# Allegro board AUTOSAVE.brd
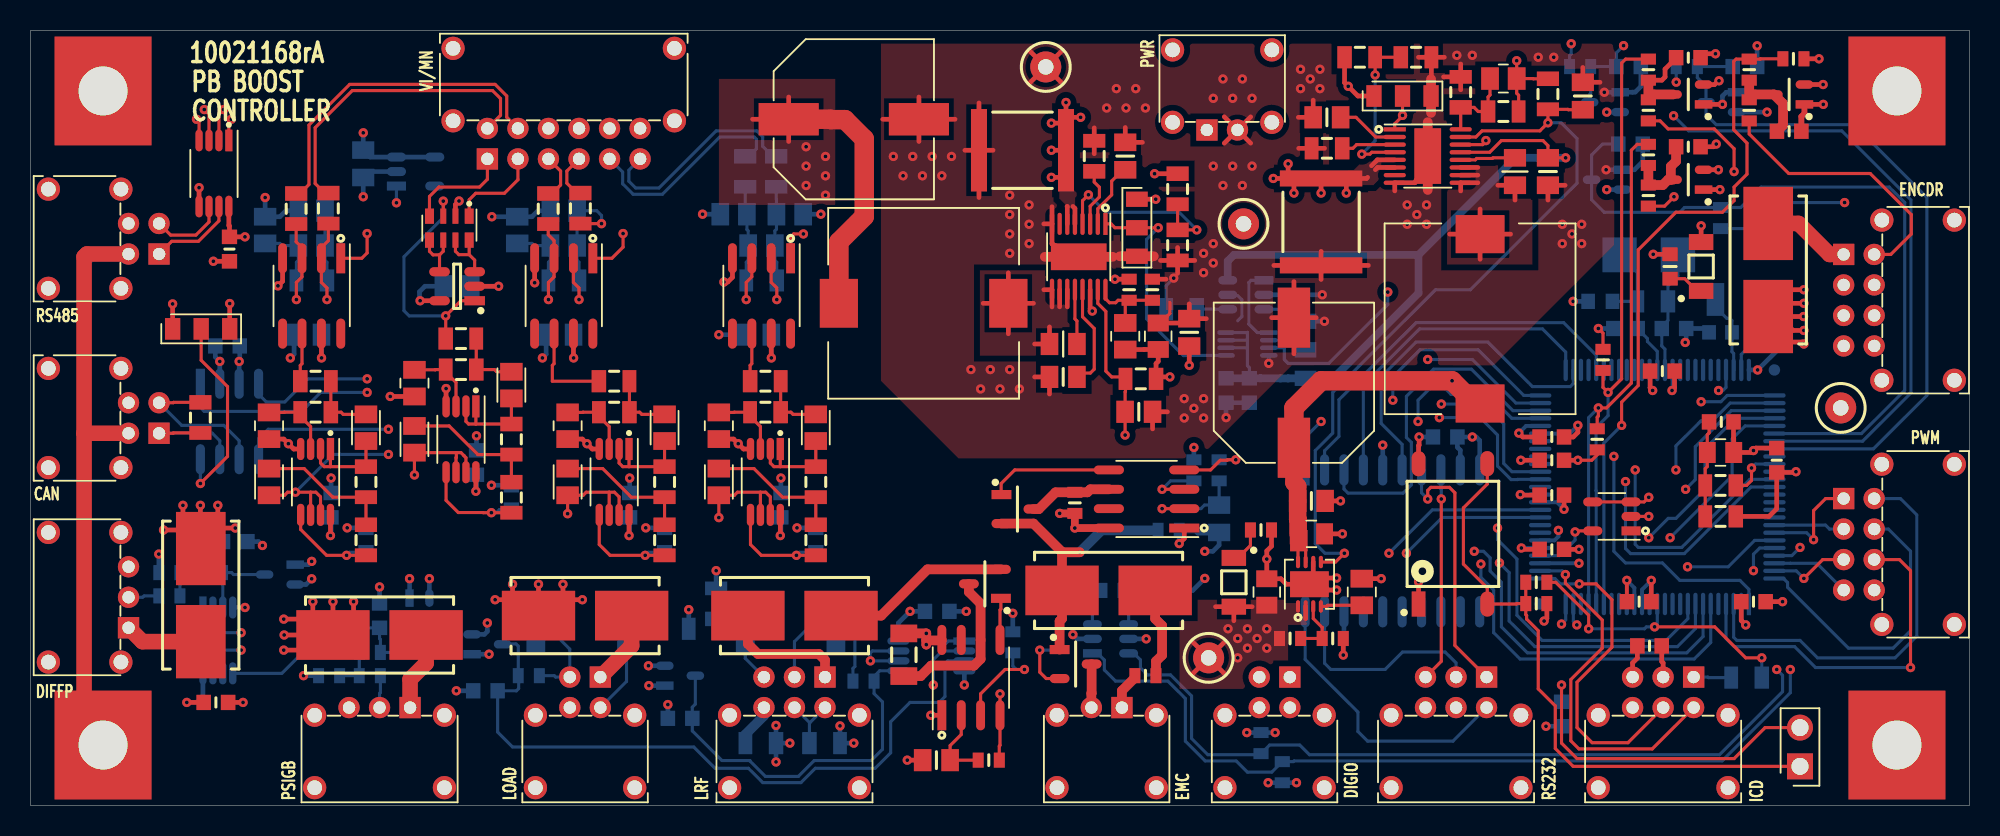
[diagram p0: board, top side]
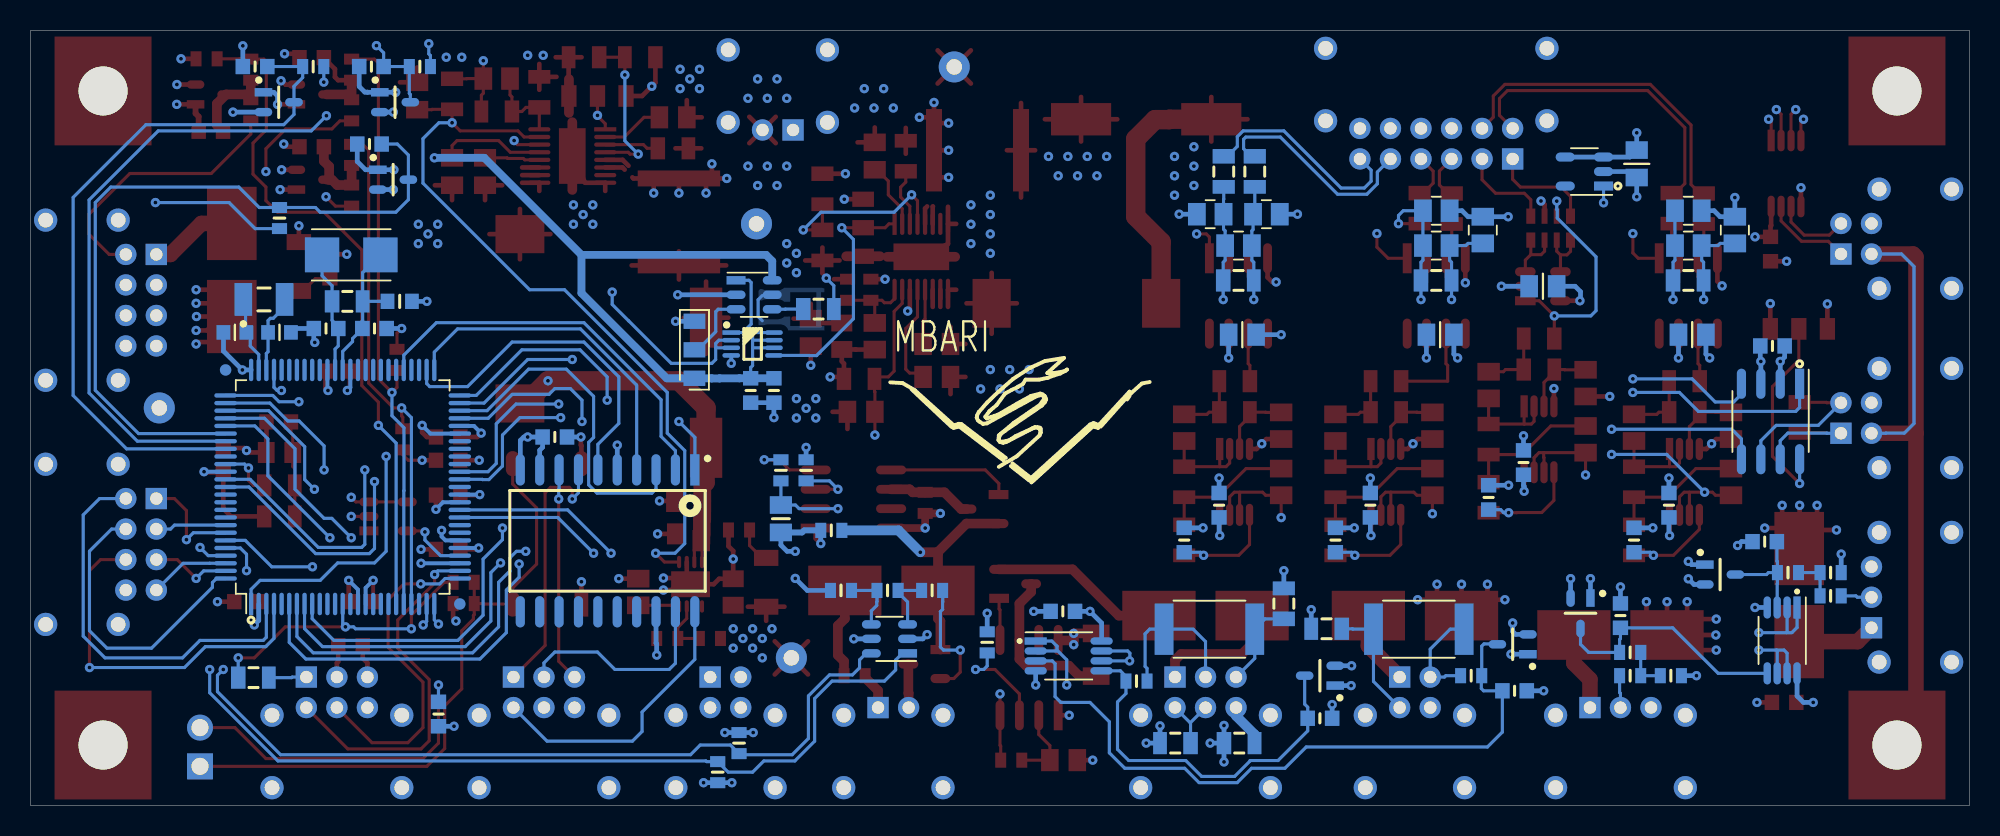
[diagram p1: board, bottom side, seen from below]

Outline 127 x 50.8 mm; copper layers: TOP, GND1, PWR, INR1, GND2, BOTTOM. Coordinates in mm from the lower left corner of the outline.
Outline path: 0,50.8 0,0 127,0 127,50.8 0,50.8

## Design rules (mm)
net group ASIG_IBOOST: nets ASIG_IBOOST+ ASIG_IBOOST-
net group ASIG_IBUS: nets ASIG_IBUS+ ASIG_IBUS-
net group ASIG_ILOAD: nets ASIG_ILOAD+ ASIG_ILOAD-
net group ASIG_VBUS: nets ASIG_VBUS+ ASIG_VBUS-

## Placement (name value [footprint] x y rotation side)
C1  10uF  [CAPC2012X135N]  110.69 23.14 0 top
C2  0.10uF  [CAPC1608X87N]  110.74 25.15 0 top
C3  0.10uF  [CAPC1608X87N]  100.28 5.99 270 bottom
C4  22pF  [CAPC1608X90N_G100]  113.61 31.01 0 bottom
C5  22pF  [CAPC1608X90N_G100]  110.69 31.01 180 bottom
C6  33pF  [CAPC1608X90N]  104.47 31.27 180 bottom
C7  33pF  [CAPC1608X90N]  107.65 31.27 0 bottom
C8  0.10uF  [CAPC1608X87N]  112.85 13.36 0 top
C9  0.10uF  [CAPC1608X87N]  105.36 13.36 0 top
C10  0.10uF  [CAPC1608X87N]  99.64 16.79 0 top
C11  0.10uF  [CAPC1608X87N]  99.64 20.35 0 top
C12  0.10uF  [CAPC1608X87N]  99.64 24.16 0 top
C13  0.10uF  [CAPC1608X87N]  106.88 28.47 0 top
C14  0.10uF  [CAPC1608X87N]  114.38 22.63 90 top
C15  0.10uF  [CAPC1608X87N]  99.64 22.63 0 top
C16  10.0pF  [CAPC2012X88N]  96.47 47.65 0 top
C17  1.0uF  [CAPC2012X140N]  99.39 41.55 270 top
C18  0.1uF  [CAPC2013X94N]  97.23 41.55 270 top
C19  0.10uF  [CAPC2012X110N]  84.91 45.11 180 top
C20  10uF  [CAPC5750X250N]  84.53 38.25 270 top
C21  10uF  [CAPC2012X135N]  83.9 17.81 0 top
C22  0.10uF  [CAPC2012X110N]  83.9 19.96 0 top
C23  2200uF  [CAPAE1030X1380DD450L320N]  82.75 27.71 90 top
C24  10uF  [CAPC2012X135N]  80.98 14 90 top
C25  0.10uF  [CAPC2012X100N]  101.68 46.51 90 top
C26  1000.0pF  [CAPC2012X88N]  87.2 14 90 top
C27  0.10uF  [CAPC1608X87N]  78.31 27.2 270 bottom
C28  0.10uF  [CAPC1608X87N]  79.83 27.2 270 bottom
C29  10.0pF  [CAPC2012X88N]  71.7 30.76 270 top
C30  1.0uF  [CAPC2012X140N]  67.64 28.09 180 top
C31  0.1uF  [CAPC2013X94N]  67.64 30.25 180 top
C32  0.10uF  [CAPC2012X110N]  71.7 42.57 90 top
C33  10uF  [CAPC5750X250N]  64.97 42.95 180 top
C34  10uF  [CAPC2012X135N]  73.86 30.76 90 top
C35  0.10uF  [CAPC2012X110N]  75.9 31.01 90 top
C36  2200uF  [CAPAE1030X1380DD450L320N]  53.92 44.98 0 top
C37  0.10uF  [CAPC2012X100N]  72.59 25.81 0 top
C38  0.10uF  [CAPC1608X87N]  12.9 30.12 180 bottom
C39  0.10uF  [CAPC1608X87N]  106.05 10.46 180 top
C40  0.10uF  [CAPC1608X87N]  13.03 36.47 270 top
C41  0.10uF  [CAPC1608X87N]  92.66 24.16 180 bottom
C42  0.1uF  [CAPC2013X94N]  27.94 34.04 0 bottom
C43  680pF  [CAPC2012X88N]  25.15 27.69 270 top
C44  560pF  [CAPC1608X90N]  31.5 20.19 90 bottom
C45  6800pF  [CAPC2012X90N]  31.5 27.56 270 top
C46  6800pF  [CAPC2012X90N]  25.15 24 270 top
C47  0.10uF  [CAPC1608X87N]  29.21 22.48 90 bottom
C48  10,000.0pF  [CAPC2012X88N]  34.92 38.99 0 bottom
C49  0.1uF  [CAPC2013X94N]  34.67 30.86 180 bottom
C50  10,000.0pF  [CAPC2012X88N]  34.92 36.7 180 bottom
C51  680pF  [CAPC2012X88N]  35.18 24.89 270 top
C52  560pF  [CAPC1608X90N]  41.53 17.4 90 bottom
C53  10,000.0pF  [CAPC2012X88N]  31.88 37.72 90 bottom
C54  6800pF  [CAPC2012X90N]  41.53 24.77 270 top
C55  6800pF  [CAPC2012X90N]  35.18 21.21 270 top
C56  0.10uF  [CAPC1608X87N]  39.24 19.68 90 bottom
C57  10,000.0pF  [CAPC2012X88N]  49.73 38.76 180 bottom
C58  0.1uF  [CAPC2013X94N]  47.62 30.86 180 bottom
C59  10,000.0pF  [CAPC2012X88N]  47.88 36.7 180 bottom
C60  680pF  [CAPC2012X88N]  45.09 24.89 270 top
C61  560pF  [CAPC1608X90N]  51.44 17.4 90 bottom
C62  10,000.0pF  [CAPC2012X88N]  46.05 38.76 180 bottom
C63  6800pF  [CAPC2012X90N]  51.44 24.77 270 top
C64  6800pF  [CAPC2012X90N]  45.09 21.21 270 top
C65  0.10uF  [CAPC1608X87N]  49.15 19.68 90 bottom
C66  10,000.0pF  [CAPC2012X88N]  18.41 38.99 0 bottom
C67  0.1uF  [CAPC2013X94N]  18.16 30.86 180 bottom
C68  10,000.0pF  [CAPC2012X88N]  18.41 36.7 180 bottom
C69  680pF  [CAPC2012X88N]  15.62 24.89 270 top
C70  560pF  [CAPC1608X90N]  21.97 17.4 90 bottom
C71  10,000.0pF  [CAPC2012X88N]  15.37 37.72 90 bottom
C72  6800pF  [CAPC2012X90N]  21.97 24.77 270 top
C73  6800pF  [CAPC2012X90N]  15.62 21.21 270 top
C74  0.10uF  [CAPC1608X87N]  19.68 19.68 90 bottom
C75  0.1uF  [CAPC2013X94N]  21.79 42.06 270 bottom
C76  0.10uF  [CAPC1608X87N]  13.41 17.3 0 bottom
C77  0.10uF  [CAPC1608X87N]  22.86 12.45 90 bottom
C78  0.10uF  [CAPC1608X87N]  29.79 7.52 180 bottom
C79  0.10uF  [CAPC1608X87N]  42.55 5.71 180 bottom
C80  0.10uF  [CAPC1608X87N]  12.14 6.76 0 top
C81  0.10uF  [CAPC1608X87N]  59.39 12.73 0 bottom
C82  0.47uF  [CAPC1608X87N]  104.8 43.36 0 bottom
C83  4.7uF  [CAPC2012X140N]  59.33 2.97 180 top
C84  0.47uF  [CAPC1608X87N]  104.67 48.44 0 bottom
C85  0.47uF  [CAPC1608X87N]  112.29 48.44 0 bottom
C86  4.7uF  [CAPC2012X140N]  77.85 18.8 270 bottom
C87  0.47uF  [CAPC1608X87N]  108.58 49.02 0 top
C88  0.47uF  [CAPC1608X87N]  108.58 43.18 0 top
C89  0.47uF  [CAPC1608X87N]  115.19 44.2 0 top
D1  LTST-C150KGKT  [LED_LTST-C150XXX]  78.82 14.63 270 top
D2  LTST-C150KGKT  [LED_LTST-C150XXX]  109.42 35.33 90 top
DN1  BAT54SWT1G  [SOT65P220X100-3N_132]  29.92 10.57 0 bottom
DN2  BAT54SWT1G  [SOT65P220X100-3N_132]  42.55 8.51 0 bottom
DN3  BAT54SWT1G  [SOT65P220X100-3N_132]  108.58 41.02 180 top
DN4  BAT54SWT1G  [SOT65P220X100-3N_132]  108.58 46.61 180 top
DN5  BAT54SWT1G  [SOT65P220X100-3N_132]  115.19 46.61 180 top
DN6  BAT54SWT1G  [SOT65P220X100-3N_132]  103.25 41.02 180 bottom
DN7  BAT54SWT1G  [SOT65P220X100-3N_132]  103.12 46.1 180 bottom
DN8  BAT54SWT1G  [SOT65P220X100-3N_132]  110.74 46.1 180 bottom
DN9  BAT54SWT1G  [SOT65P220X100-3N_132]  25.48 12.6 270 bottom
DN10  BAT54SWT1G  [SOT65P220X100-3N_132]  16.33 15.14 180 bottom
F1  0154.125DR  [FUSM9750X381N]  11.15 13.79 90 top
F2  0154.125DR  [FUSM9750X381N]  22.86 11.18 180 top
F3  0154.125DR  [FUSM9750X381N]  36.32 12.45 180 top
F4  0154.125DR  [FUSM9750X381N]  50.04 12.45 0 top
F5  0154.125DR  [FUSM9750X381N]  113.82 35.1 270 top
F6  0154.125DR  [FUSM9750X381N]  70.61 14.1 180 top
J1  M80-8420242  [HARWIN_M80-8420242]  78.05 47.65 180 top
J2  M80-8510442  [HARWIN_M80-8510442]  3.05 25.4 270 top
J3  M80-8510642  [HARWIN_M80-8510642]  106.93 3.05 0 top
J4  M80-8510442  [HARWIN_M80-8510442]  3.05 37.15 270 top
J5  M80-8510642  [HARWIN_M80-8510642]  93.37 3.05 0 top
J6  M80-8511242  [HARWIN_M80-8511242]  34.92 47.75 180 top
J7  M80-8420342  [HARWIN_M80-8420342]  3.05 13.65 270 top
J8  M80-8420342  [HARWIN_M80-8420342]  22.86 3.05 0 top
J9  M80-8510442  [HARWIN_M80-8510442]  36.32 3.05 0 top
J10  M80-8510642  [HARWIN_M80-8510642]  50.04 3.05 0 top
J11  M80-8510842  [HARWIN_M80-8510842]  124.13 33.12 90 top
J12  M80-8510842  [HARWIN_M80-8510842]  124.13 17.12 90 top
J13  M80-8420242  [HARWIN_M80-8420242]  70.48 3.05 0 top
J14  M80-8510442  [HARWIN_M80-8510442]  81.48 3.05 0 top
JP1  LS=0.100"  [HDRV2W64P254_2X1_508X254H1363B]  115.9 2.57 90 top
JR1  TBD  [MISC_0805-3P-JMPR]  89.87 46.51 0 top
JR2  TBD  [MISC_0805-3P-JMPR]  83.52 29.87 90 bottom
JR3  TBD  [MISC_0805-3P-JMPR]  72.47 37.87 270 top
JR4  TBD  [MISC_0805-3P-JMPR]  11.18 31.24 0 top
L1  220uH  [IND_NS-12]  94.95 31.9 270 top
L2  220uH  [IND_NS-12]  58.5 32.92 180 top
NOREF  -  []  0 0 0 top
NOREF#2  -  []  256.03 33.78 0 top
NOREF#3  -  []  144.78 -66.04 0 top
NOREF#4  -  []  0 0 90 top
NOREF#5  -  []  -50.8 -76.2 0 top
NOREF#6  -  [unnamed#2]  122.25 46.84 0 top
NOREF#7  -  [unnamed#2]  122.25 3.96 0 top
NOREF#8  -  []  0 0 0 top
NOREF#9  -  []  0 0 90 top
NOREF#10  -  []  0 0 0 top
NOREF#11  -  [unnamed#2]  4.75 3.96 0 top
NOREF#12  -  []  127 0 90 top
NOREF#13  -  [unnamed#2]  4.75 46.84 0 top
NOREF#14  -  []  -50.8 -76.2 0 top
NOREF#15  -  []  61.47 30.35 180 bottom
Q1  SI2308DS-T1-E3  [SOT95P237X112-3N_132]  62.51 14.53 180 top
Q2  SI2308DS-T1-E3  [SOT95P237X112-3N_132]  64.64 19.43 0 top
Q3  SI2308DS-T1-E3  [SOT95P237X112-3N_132]  68.45 9.27 0 top
R1  TBD  [RESC2012X50N]  110.69 18.95 180 top
R2  0.0  [RESC2012X50N]  110.69 20.98 180 top
R3  4.70K  [RESC1608X50N]  98.63 13.23 180 top
R4  1.00K  [RESC1608X50N]  98.63 14.63 0 top
R5  0.0  [RESC1609X55N]  102.82 33.05 0 bottom
R6  1.00M  [RESC2012X50N]  106.25 33.05 180 bottom
R7  360.0K  [RESC1608X50N]  82.5 10.95 0 top
R8  620.0K  [RESC2012X50N]  96.47 45.49 0 top
R9  243.0K  [RESC2012X50N]  93.68 46.76 90 top
R10  205.0K  [RESC1608X50N]  85.29 10.95 0 top
R11  232.0K  [RESC2012X50N]  84.91 43.08 180 top
R12  20.0K  [RESC2012X50N]  99.39 46.63 270 top
R13  309.0K  [RESC2012X50N]  87.07 49.05 0 top
R14  64.9  [RESC1608X50N]  80.59 18.06 0 top
R15  619.0K  [RESC2012X50N]  90.75 49.05 0 top
R16  249.0K  [RESC2012X50N]  75.39 32.54 180 bottom
R17  1.00M  [RESC1608X50N]  71.96 33.81 90 top
R18  243.0K  [RESC1608X50N]  73.48 33.81 90 top
R19  232.0K  [RESC2012X50N]  69.67 42.57 90 top
R20  20.0K  [RESC2012X50N]  72.72 27.97 180 top
R21  309.0K  [RESC2012X50N]  75.13 40.41 270 top
R22  150  [RESC1609X55N]  107.39 35.33 90 top
R23  619.0K  [RESC2012X50N]  75.13 36.73 270 top
R24  100  [RESC2012X50N]  112.39 8.38 180 bottom
R25  120  [RESC2012X50N]  11.13 25.43 270 top
R26  5.62K  [RESC2012X50N]  28.19 30.61 0 top
R27  160.0K  [RESC2012X50N]  28.19 28.57 180 top
R28  33.2K  [RESC2012X50N]  31.5 24 270 top
R29  33.2K  [RESC2012X50N]  31.5 20.19 270 top
R30  1.62K  [RESC2012X50N]  36.02 39.14 270 top
R31  10.2K  [RESC2012X50N]  34.92 34.42 180 bottom
R32  5.62K  [RESC2012X50N]  38.23 27.81 0 top
R33  160.0K  [RESC2012X50N]  38.23 25.78 180 top
R34  33.2K  [RESC2012X50N]  41.53 21.21 270 top
R35  33.2K  [RESC2012X50N]  41.53 17.4 270 top
R36  1.78K  [RESC2012X50N]  33.91 39.12 270 top
R37  1.62K  [RESC2012X50N]  48.84 41.55 270 bottom
R38  10.2K  [RESC2012X50N]  47.88 34.42 180 bottom
R39  5.62K  [RESC2012X50N]  48.13 27.81 0 top
R40  160.0K  [RESC2012X50N]  48.13 25.78 180 top
R41  33.2K  [RESC2012X50N]  51.44 21.21 270 top
R42  33.2K  [RESC2012X50N]  51.44 17.4 270 top
R43  1.78K  [RESC2012X50N]  46.81 41.55 270 bottom
R44  1.62K  [RESC2012X50N]  19.51 39.14 270 top
R45  10.2K  [RESC2012X50N]  18.41 34.42 180 bottom
R46  5.62K  [RESC2012X50N]  18.67 27.81 0 top
R47  160.0K  [RESC2012X50N]  18.67 25.78 180 top
R48  33.2K  [RESC2012X50N]  21.97 21.21 270 top
R49  33.2K  [RESC2012X50N]  21.97 17.4 270 top
R50  1.78K  [RESC2012X50N]  17.4 39.12 270 top
R51  10.0K  [RESC1608X50N]  9.09 13.74 0 bottom
R52  16.2K  [RESC1608X50N]  11.89 15.27 0 bottom
R53  4.53K  [RESC1608X50N]  9.09 15.27 0 bottom
R54  10.0K  [RESC1608X50N]  22.23 8.51 180 bottom
R55  16.2K  [RESC1608X50N]  22.23 10.03 0 bottom
R56  4.53K  [RESC1608X50N]  19.56 8.51 0 bottom
R57  16.2K  [RESC1608X50N]  32.64 8.51 0 bottom
R58  150  [RESC6332X70N]  36.07 11.56 0 bottom
R59  0.0  [RESC2012X50N]  42.11 11.58 0 bottom
R60  16.2K  [RESC1608X50N]  54.56 8.15 180 bottom
R61  0.0  [RESC2012X50N]  44.91 13.23 90 bottom
R62  150  [RESC6332X70N]  49.78 11.56 180 bottom
R63  10  [RESC1608X50N]  105.97 39.98 90 top
R64  2.20K  [RESC1608X50N]  105.97 42.65 90 top
R65  4.30K  [RESC1608X50N]  102.62 24 270 top
R66  10  [RESC1608X50N]  105.97 45.57 90 top
R67  2.20K  [RESC1608X50N]  105.97 48.23 90 top
R68  4.30K  [RESC1608X50N]  103 29.21 90 top
R69  10  [RESC1608X50N]  112.57 45.57 90 top
R70  2.20K  [RESC1608X50N]  112.57 48.23 90 top
R71  4.30K  [RESC1608X50N]  115.47 48.95 0 top
R72  10.0K  [RESC1608X50N]  64.34 10.69 270 bottom
R73  0.05  [RESC3116X65N]  57.2 9.88 270 top
R74  2.00K  [RESC1608X50N]  62.76 2.97 180 top
R75  330  [RESC1608X50N]  110.69 38.51 90 bottom
R76  330  [RESC1608X50N]  101.5 48.44 0 bottom
R77  10.0K  [RESC1608X50N]  76.2 21.97 270 bottom
R78  51.1  [RESC1608X50N]  68.4 19.84 90 top
R79  330  [RESC1608X50N]  108.48 48.44 0 bottom
R80  2.00K  [RESC1608X50N]  77.85 21.97 270 bottom
R81  7.15K  [RESC1608X50N]  73.03 8.51 180 top
R82  1.00M  [RESC1608X50N]  74.55 18.03 0 bottom
R83  10.0K  [RESC1608X50N]  81.99 2.18 90 bottom
R84  7.15K  [RESC1608X50N]  67.94 14.1 0 bottom
R85  10.0K  [RESC1608X50N]  80.59 4.09 270 bottom
R86  511  [RESC1608X50N]  70.87 14.1 0 bottom
R87  1.21K  [RESC1608X50N]  73.91 14.1 0 bottom
R88  0.0  [RESC2012X50N]  47.83 4.09 180 bottom
R89  0.0  [RESC2012X50N]  52.02 4.09 0 bottom
RN1  10k,15k  [RESCAXS80P150X150X55-8N]  27.43 37.85 180 top
SW1  FSM2JSMA  [SOIC450P1000X459R-4N]  93.17 17.81 90 top
TP1  RED  [TP_KEYSTONE_5000S_MINI]  79.45 38.13 0 top
TP2  BLACK  [TP_KEYSTONE_5000S_MINI]  66.5 48.41 0 top
TP3  YELLOW  [TP_KEYSTONE_5000S_MINI]  77.17 9.68 180 top
TP4  ORANGE  [TP_KEYSTONE_5000S_MINI]  118.57 26.06 0 top
U1  DSPIC33FJ256MC710A-H/PF  [QFP50P1600X1600X120-100L30N]  106.55 20.88 180 bottom
U2  REF1933AIDDCT  [SOT95P280X110-5L30N]  103.58 18.95 90 top
U3  LT8610ABEMSE#PBF  [SOP50P490X110-17L30T175X364N]  91.52 42.57 270 top
U4  ADM7171ACPZ-3.3-R7  [SON50P300X300X80-9T170X254N]  83.77 14.5 0 top
U5  SN74AUP1G74DCUR  [SOP50P310X90-8N]  79.71 30.25 180 bottom
U6  LTC6906CS6#TRMPBF  [SOT95P280X100-6L20N]  79.6 33.48 270 bottom
U7  LT8610ABEMSE#PBF  [SOP50P490X110-17L30T175X364N]  68.66 35.97 180 top
U8  SN65HVD233D  [SOIC127P600X175-8L87N]  13.03 25.17 0 bottom
U9  MAX3233EEWP+G36  [SOIC127P1032X265-20N]  89.2 17.35 270 bottom
U10  MAX3471EUA+  [SOP65P490X110-8L25N]  12.01 41.43 180 top
U11  LTC2054CS5#TRMPBF  [SOT95P280X100-5N]  27.94 34.04 180 top
U12  LTC2055HVHMS8#PBF  [SOP65P490X110-8L30N]  28.19 24 180 top
U13  LT1990ACS8#PBF  [SOIC127P599X175-8L86N]  34.92 33.4 180 top
U14  LTC2055HVHMS8#PBF  [SOP65P490X110-8L30N]  38.23 21.21 180 top
U15  LT1990ACS8#PBF  [SOIC127P599X175-8L86N]  47.88 33.4 180 top
U16  LTC2055HVHMS8#PBF  [SOP65P490X110-8L30N]  48.13 21.21 180 top
U17  LT1990ACS8#PBF  [SOIC127P599X175-8L86N]  18.41 33.4 180 top
U18  LTC2055HVHMS8#PBF  [SOP65P490X110-8L30N]  18.67 21.21 180 top
U19  REF1930AIDDCT  [SOT95P280X110-5L30N]  25.22 41.55 90 bottom
U20  LTC2055HVHMS8#PBF  [SOP65P490X110-8L30N]  12.27 10.82 0 bottom
U21  LTC2055HVHMS8#PBF  [SOP65P490X110-8L30N]  59 9.8 270 bottom
U22  LT1910ES8#PBF  [SOIC127P599X175-8L86N]  61.59 8.38 0 top
U23  LT1910ES8#PBF  [SOIC127P599X175-8L86N]  73.1 20.09 90 top
U24  LT6700CS6-1#TRMPBF  [SOT95P280X100-6L20N]  70.74 10.92 90 bottom
Y1  32.768kHz  [OSCCC150X320X90-2N]  111.71 33.17 90 bottom
Y2  8MHz  [XTALSC500X500X135-2N]  105.99 36.09 0 bottom

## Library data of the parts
C1-C22 C24-C35 C37-C89 = CAP
C23 C36 = CAP_P
D1 D2 = LED
DN1-DN10 = DIODE_DUAL_ACJ
F1-F6 = FUSEHOLDER_2T_2PIN
J1 J13 = CON2
J2 J4 J9 J14 = CON4
J3 J5 J10 = CON6
J6 = CON12
J7 J8 = CON3
J11 J12 = CON8
JP1 = JUMPER_2PIN
JR1-JR4 = RES_3PIN-JMPR
L1 L2 = IND_FERRITE
Q1-Q3 = MOSFET_I_EN_GSD
R1-R89 = RES
RN1 = RES_ARRAY_4
SW1 = SW_SPST_12_34
TP1-TP4 = TESTPOINT
U1 = dsPIC33F_100TQFP
U2 U19 = REF19xx
U3 U7 = LT8610A
U4 = ADM7171
U5 = 74xxx1G74DC-DLatch
U6 = LTC6906_S6
U8 = SN65HVD233
U9 = MAX3233E
U10 = MAX3471xUA
U11 = LTC2054_S5
U12 U14 U16 U18 U20 U21 = LTC2055_MS8
U13 U15 U17 = LT1990
U22 U23 = LT1910
U24 = LT6700-1
Y1 Y2 = CRYSTAL

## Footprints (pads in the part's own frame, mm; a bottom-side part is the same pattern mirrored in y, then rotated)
CAPAE1030X1380DD450L320N
  rect 3.94x2.121 smd: 1(-4.265,0) 2(4.265,0)
CAPC1608X87N
  rect 0.95x1.001 smd: 1(-0.8,0) 2(0.8,0)
CAPC1608X90N
  rect 0.95x1.001 smd: 1(-0.8,0) 2(0.8,0)
CAPC1608X90N_G100
  rect 0.899x0.95 smd: 1(-0.749,0) 2(0.749,0)
CAPC2012X88N
  rect 1.161x1.471 smd: 1(-0.874,0) 2(0.874,0)
CAPC2012X90N
  rect 1.161x1.471 smd: 1(-0.874,0) 2(0.874,0)
CAPC2012X100N
  rect 1.151x1.45 smd: 1(-0.899,0) 2(0.899,0)
CAPC2012X110N
  rect 1.151x1.45 smd: 1(-0.899,0) 2(0.899,0)
CAPC2012X135N
  rect 1.1x1.379 smd: 1(-0.866,0) 2(0.866,0)
CAPC2012X140N
  rect 1.151x1.45 smd: 1(-0.899,0) 2(0.899,0)
CAPC2013X94N
  rect 1.151x1.45 smd: 1(-0.899,0) 2(0.899,0)
CAPC5750X250N
  rect 1.049x5.4 smd: 1(-2.85,0) 2(2.85,0)
FUSM9750X381N
  rect 4.801x3.251 smd: 1(-3.051,0) 2(3.051,0)
HARWIN_M80-8420242
  round 1.524 hole 0.965: (-3.251,2.87) (-3.251,-1.88) (3.251,2.87) (3.251,-1.88)
  rect 1.397x1.397 hole 0.813: 1(1.001,3.371)
  round 1.397 hole 0.813: 2(-1.001,3.371)
HARWIN_M80-8420342
  round 1.524 hole 0.965: (-4.249,2.87) (-4.249,-1.88) (4.249,2.87) (4.249,-1.88)
  rect 1.397x1.397 hole 0.813: 1(1.999,3.371)
  round 1.397 hole 0.813: 2(0,3.371) 3(-1.999,3.371)
HARWIN_M80-8510442
  round 1.524 hole 0.965: (-3.251,2.87) (-3.251,-1.88) (3.251,2.87) (3.251,-1.88)
  rect 1.397x1.397 hole 0.813: 1(1.001,5.37)
  round 1.397 hole 0.813: 2(-1.001,5.37) 3(1.001,3.371) 4(-1.001,3.371)
HARWIN_M80-8510642
  round 1.524 hole 0.965: (-4.249,2.87) (-4.249,-1.88) (4.249,2.87) (4.249,-1.88)
  rect 1.397x1.397 hole 0.813: 1(1.999,5.37)
  round 1.397 hole 0.813: 2(0,5.37) 3(-1.999,5.37) 4(1.999,3.371) 5(0,3.371) 6(-1.999,3.371)
HARWIN_M80-8510842
  round 1.524 hole 0.965: (-5.25,2.87) (-5.25,-1.88) (5.25,2.87) (5.25,-1.88)
  rect 1.397x1.397 hole 0.813: 1(3,5.37)
  round 1.397 hole 0.813: 2(1.001,5.37) 3(-1.001,5.37) 4(-3,5.37) 5(3,3.371) 6(1.001,3.371) 7(-1.001,3.371) 8(-3,3.371)
HARWIN_M80-8511242
  round 1.524 hole 0.965: (-7.249,2.87) (-7.249,-1.88) (7.249,2.87) (7.249,-1.88)
  rect 1.397x1.397 hole 0.813: 1(5.001,5.37)
  round 1.397 hole 0.813: 2(3,5.37) 3(1.001,5.37) 4(-1.001,5.37) 5(-3,5.37) 6(-5.001,5.37) 7(5.001,3.371) 8(3,3.371) 9(1.001,3.371) 10(-1.001,3.371) 11(-3,3.371) 12(-5.001,3.371)
HDRV2W64P254_2X1_508X254H1363B
  rect 1.702x1.702 hole 1.118: 1(0,0)
  round 1.702 hole 1.118: 2(2.54,0)
IND_NS-12
  rect 2.499x3.2 smd: 1(-5.55,0) 2(5.55,0)
LED_LTST-C150XXX
  rect 1.049x1.6 smd: A(1.6,0) C(-1.6,0)
MISC_0805-3P-JMPR
  rect 1.001x1.42 smd: 1(-1.869,0) 2(0,0) 3(1.869,0)
OSCCC150X320X90-2N
  rect 2.149x1.151 smd: 1(0,1.349) 2(0,-1.349)
QFP50P1600X1600X120-100L30N
  round 0.749 smd: (-7.671,7.671) (7.671,-7.671)
  rect 0.279x1.471 smd: 1(-5.999,-7.671)
  oval 0.279x1.471 smd: 2(-5.499,-7.671) 3(-5.001,-7.671) 4(-4.501,-7.671) 5(-4,-7.671) 6(-3.5,-7.671) 7(-3,-7.671) 8(-2.499,-7.671) 9(-1.999,-7.671) 10(-1.501,-7.671) 11(-1.001,-7.671) 12(-0.5,-7.671) 13(0,-7.671) 14(0.5,-7.671) 15(1.001,-7.671) 16(1.501,-7.671) 17(1.999,-7.671) 18(2.499,-7.671) 19(3,-7.671) 20(3.5,-7.671) 21(4,-7.671) 22(4.501,-7.671) 23(5.001,-7.671) 24(5.499,-7.671) 25(5.999,-7.671) 51(5.999,7.671) 52(5.499,7.671) 53(5.001,7.671) 54(4.501,7.671) 55(4,7.671) 56(3.5,7.671) 57(3,7.671) 58(2.499,7.671) 59(1.999,7.671) 60(1.501,7.671) 61(1.001,7.671) 62(0.5,7.671) 63(0,7.671) 64(-0.5,7.671) 65(-1.001,7.671) 66(-1.501,7.671) 67(-1.999,7.671) 68(-2.499,7.671) 69(-3,7.671) 70(-3.5,7.671) 71(-4,7.671) 72(-4.501,7.671) 73(-5.001,7.671) 74(-5.499,7.671) 75(-5.999,7.671)
  oval 1.471x0.279 smd: 26(7.671,-5.999) 27(7.671,-5.499) 28(7.671,-5.001) 29(7.671,-4.501) 30(7.671,-4) 31(7.671,-3.5) 32(7.671,-3) 33(7.671,-2.499) 34(7.671,-1.999) 35(7.671,-1.501) 36(7.671,-1.001) 37(7.671,-0.5) 38(7.671,0) 39(7.671,0.5) 40(7.671,1.001) 41(7.671,1.501) 42(7.671,1.999) 43(7.671,2.499) 44(7.671,3) 45(7.671,3.5) 46(7.671,4) 47(7.671,4.501) 48(7.671,5.001) 49(7.671,5.499) 50(7.671,5.999) 76(-7.671,5.999) 77(-7.671,5.499) 78(-7.671,5.001) 79(-7.671,4.501) 80(-7.671,4) 81(-7.671,3.5) 82(-7.671,3) 83(-7.671,2.499) 84(-7.671,1.999) 85(-7.671,1.501) 86(-7.671,1.001) 87(-7.671,0.5) 88(-7.671,0) 89(-7.671,-0.5) 90(-7.671,-1.001) 91(-7.671,-1.501) 92(-7.671,-1.999) 93(-7.671,-2.499) 94(-7.671,-3) 95(-7.671,-3.5) 96(-7.671,-4) 97(-7.671,-4.501) 98(-7.671,-5.001) 99(-7.671,-5.499) 100(-7.671,-5.999)
RESC1608X50N
  rect 0.719x0.991 smd: 1(-0.691,0) 2(0.691,0)
RESC1609X55N
  rect 0.899x1.001 smd: 1(-0.8,0) 2(0.8,0)
RESC2012X50N
  rect 0.95x1.45 smd: 1(-1.001,0)
  rect 0.899x1.45 smd: 2(1.001,0)
RESC3116X65N
  rect 1.151x1.75 smd: 1(-1.4,0) 2(1.4,0)
RESC6332X70N
  rect 1.229x3.371 smd: 1(-2.969,0) 2(2.969,0)
RESCAXS80P150X150X55-8N
  rect 0.589x1.001 smd: 1(-1.3,-0.785) 4(1.3,-0.785) 5(1.3,0.785) 8(-1.3,0.785)
  rect 0.391x1.001 smd: 2(-0.399,-0.785) 3(0.399,-0.785) 6(0.399,0.785) 7(-0.399,0.785)
SOIC127P599X175-8L86N
  rect 0.579x1.971 smd: 1(-1.905,-2.469)
  oval 0.579x1.971 smd: 2(-0.635,-2.469) 3(0.635,-2.469) 4(1.905,-2.469) 5(1.905,2.469) 6(0.635,2.469) 7(-0.635,2.469) 8(-1.905,2.469)
SOIC127P600X175-8L87N
  rect 0.599x1.971 smd: 1(-1.905,-2.474)
  oval 0.599x1.971 smd: 2(-0.635,-2.474) 3(0.635,-2.474) 4(1.905,-2.474) 5(1.905,2.474) 6(0.635,2.474) 7(-0.635,2.474) 8(-1.905,2.474)
SOIC127P1032X265-20N
  rect 2.05x0.599 smd: 1(-4.651,5.715)
  oval 2.05x0.599 smd: 2(-4.651,4.445) 3(-4.651,3.175) 4(-4.651,1.905) 5(-4.651,0.635) 6(-4.651,-0.635) 7(-4.651,-1.905) 8(-4.651,-3.175) 9(-4.651,-4.445) 10(-4.651,-5.715) 11(4.651,-5.715) 12(4.651,-4.445) 13(4.651,-3.175) 14(4.651,-1.905) 15(4.651,-0.635) 16(4.651,0.635) 17(4.651,1.905) 18(4.651,3.175) 19(4.651,4.445) 20(4.651,5.715)
SOIC450P1000X459R-4N
  rect 1.651x0.899 smd: 1(-4.6,2.25)
  oval 1.651x0.899 smd: 2(4.6,2.25) 3(4.6,-2.25) 4(-4.6,-2.25)
SON50P300X300X80-9T170X254N
  oval 0.269x0.81 smd: 1(-0.749,-1.455) 2(-0.249,-1.455) 3(0.249,-1.455) 4(0.749,-1.455) 5(0.749,1.455) 6(0.249,1.455) 7(-0.249,1.455) 8(-0.749,1.455)
  rect 2.54x1.699 smd: 9(0,0)
SOP50P310X90-8N
  rect 1.151x0.3 smd: 1(-1.4,0.749)
  oval 1.151x0.3 smd: 2(-1.4,0.249) 3(-1.4,-0.249) 4(-1.4,-0.749) 5(1.4,-0.749) 6(1.4,-0.249) 7(1.4,0.249) 8(1.4,0.749)
SOP50P490X110-17L30T175X364N
  rect 0.279x1.45 smd: 1(-1.75,-2.159)
  oval 0.279x1.45 smd: 2(-1.25,-2.159) 3(-0.749,-2.159) 4(-0.249,-2.159) 5(0.249,-2.159) 6(0.749,-2.159) 7(1.25,-2.159) 8(1.75,-2.159) 9(1.75,2.159) 10(1.25,2.159) 11(0.749,2.159) 12(0.249,2.159) 13(-0.249,2.159) 14(-0.749,2.159) 15(-1.25,2.159) 16(-1.75,2.159)
  rect 3.647x1.753 smd: 17(0,0)
SOP65P490X110-8L25N
  rect 0.47x1.42 smd: 1(-0.975,-2.164)
  oval 0.47x1.42 smd: 2(-0.325,-2.164) 3(0.325,-2.164) 4(0.975,-2.164) 5(0.975,2.164) 6(0.325,2.164) 7(-0.325,2.164) 8(-0.975,2.164)
SOP65P490X110-8L30N
  rect 0.48x1.45 smd: 1(-0.975,-2.159)
  oval 0.48x1.45 smd: 2(-0.325,-2.159) 3(0.325,-2.159) 4(0.975,-2.159) 5(0.975,2.159) 6(0.325,2.159) 7(-0.325,2.159) 8(-0.975,2.159)
SOT65P220X100-3N_132
  rect 1.151x0.551 smd: 1(-1.001,0.65)
  oval 1.151x0.551 smd: 2(-1.001,-0.65) 3(1.001,0)
SOT95P237X112-3N_132
  rect 1.3x0.599 smd: 1(-1.049,0.95)
  oval 1.3x0.599 smd: 2(-1.049,-0.95) 3(1.049,0)
SOT95P280X100-5N
  rect 1.349x0.599 smd: 1(-1.151,0.95)
  oval 1.349x0.599 smd: 2(-1.151,0) 3(-1.151,-0.95) 4(1.151,-0.95) 5(1.151,0.95)
SOT95P280X100-6L20N
  rect 0.551x1.24 smd: 1(-0.95,-1.186)
  oval 0.551x1.24 smd: 2(0,-1.186) 3(0.95,-1.186) 4(0.95,1.186) 5(0,1.186) 6(-0.95,1.186)
SOT95P280X110-5L30N
  rect 0.589x1.25 smd: 1(-0.95,-1.255)
  oval 0.589x1.25 smd: 2(0,-1.255) 3(0.95,-1.255) 4(0.95,1.255) 5(-0.95,1.255)
TP_KEYSTONE_5000S_MINI
  round 2.032 hole 1.016: 1(0,0)
unnamed#2
  round 3.2 hole 3.2: (0,0)
XTALSC500X500X135-2N
  rect 2.25x2.281 smd: 1(-1.91,0) 2(1.91,0)

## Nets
3.3V: C8.1 C9.1 C10.1 C11.1 C12.1 C13.1 C14.1 C15.1 C24.1 C38.1 C39.1 C40.1 C41.1 C42.1 C47.1 C49.1 C56.1 C58.1 C65.1 C67.1 C74.1 C75.1 C80.1 C81.1 D1.A DN1.2(C) DN2.2(C) DN9.2(C) DN10.2(C) J3.2 J6.12 JR4.1 R1.1 R3.1 R5.1 R7.1 R72.1 R77.1 R83.1 R85.1 TP3.1(TP) U1.2(VDD#2) U1.16(VDD#16) U1.30(AVDD) U1.37(VDD#37) U1.46(VDD#46) U1.62(VDD#62) U1.86(VDD#86) U4.1(VOUT1) U4.2(VOUT2) U8.3(VCC) U9.9(VCC) U9.10(\\F\O\R\C\E\O\F\F\) U10.8(VCC) U11.5(V+) U12.8(V+) U13.7(V+) U14.8(V+) U15.7(V+) U16.8(V+) U17.7(V+) U18.8(V+) U19.3(EN) U19.4(VIN) U20.8(V+) U21.8(V+)
5V: C29.2 C34.1 C35.1 C36.1 D2.A DN3.2(C) DN4.2(C) DN5.2(C) DN6.2(C) DN7.2(C) DN8.2(C) F5.2 L2.2 R17.2 R20.1 TP4.1(TP) U2.3(EN) U2.4(VIN) U7.14(BIAS)
15V: C20.1 C33.1 F1.2 F2.2 F3.2 J1.1 J6.10 JR1.1 JR3.1 R13.1 R21.1 R78.1 R88.1 TP1.1(TP) U3.5(VIN1) U3.6(VIN2) U7.5(VIN1) U7.6(VIN2) U23.8(V+) U24.5(VS)
GND_EARTH: J2.3 J4.3
GND_SIGNAL: C1.2 C2.2 C3.2 C4.2 C5.2 C6.2 C7.2 C8.2 C9.2 C10.2 C11.2 C12.2 C13.2 C14.2 C15.2 C17.2 C19.2 C20.2 C21.2 C22.2 C23.2 C24.2 C25.2 C26.2 C27.2 C28.2 C30.2 C32.2 C33.2 C34.2 C35.2 C36.2 C37.2 C38.2 C39.2 C40.2 C41.2 C42.2 C43.2 C44.2 C47.2 C48.1 C49.2 C51.2 C52.2 C53.2 C56.2 C57.1 C58.2 C60.2 C61.2 C62.2 C65.2 C66.1 C67.2 C69.2 C70.2 C71.2 C74.2 C75.2 C76.2 C77.2 C78.2 C79.2 C80.2 C81.2 C82.2 C83.2 C84.2 C85.2 C86.2 C87.2 C88.2 C89.2 DN1.1(A) DN2.1(A) DN3.1(A) DN4.1(A) DN5.1(A) DN6.1(A) DN7.1(A) DN8.1(A) DN9.1(A) DN10.1(A) J1.2 J3.3 J5.5 J6.9 J6.11 J7.3 J8.3 J9.4 J11.2 J12.8 J14.3 J14.4 JR1.3 JR2.3 JR3.3 JR4.3 R9.2 R10.2 R11.2 R14.2 R15.2 R16.2 R18.2 R19.2 R22.2 R23.2 R53.1 R56.1 R59.2 R61.2 R65.2 R68.2 R71.2 R82.2 R87.2 R89.2 RN1.2 SW1.1 SW1.2 TP2.1(TP) U1.15(VSS#15) U1.28(VREF-/RA9) U1.31(AVSS) U1.36(VSS#36) U1.45(VSS#45) U1.65(VSS#65) U1.75(VSS#75) U2.2(GND) U3.8(GND) U3.17(GNDPAD) U4.6(GND#6) U4.9(GND#9) U5.4(GND) U6.2(GND) U7.8(GND) U7.17(GNDPAD) U8.2(GND) U9.5(FORCEON) U9.18(GND) U10.5(GND) U11.2(V-) U12.4(V-) U13.4(V-) U14.4(V-) U15.4(V-) U16.4(V-) U17.4(V-) U18.4(V-) U19.2(GND) U20.4(V-) U21.4(V-) U22.1(GND) U23.1(GND) U24.2(GND)
AN0_LOADCELL: U1.25(PGED3/AN0/CN2/RB0) U21.1(OUTA) U21.2(INA-)
AN1_POSITION: U1.24(PGEC3/AN1/CN3/RB1) U21.6(INB-) U21.7(OUTB)
AN10_DIFFPB: U1.34(AN10/RB10) U20.6(INB-) U20.7(OUTB)
AN11_TORQ_DIFFPA: U1.35(AN11/RB11) U20.1(OUTA) U20.2(INA-)
AN16_VSENSE: C46.2 U1.6(AN16/T2CK/T7CK/RC1) U12.6(INB-) U12.7(OUTB)
AN17_IBUS: C55.2 U1.7(AN17/T3CK/T6CK/RC2) U14.6(INB-) U14.7(OUTB)
AN18_ILOAD: C64.2 U1.8(AN18/T4CK/T9CK/RC3) U16.6(INB-) U16.7(OUTB)
AN19_IBOOST: C73.2 U1.9(AN19/T5CK/T8CK/RC4) U18.6(INB-) U18.7(OUTB)
ASIG_IBOOST+: J6.8 R50.1
ASIG_IBOOST-: J6.7 R44.1
ASIG_IBOOST_3V: R46.1 U17.6(OUT)
ASIG_IBUS+: J6.3 R36.1
ASIG_IBUS-: J6.4 R30.1
ASIG_IBUS_3V: R32.1 U13.6(OUT)
ASIG_ILOAD+: J6.5 R43.1
ASIG_ILOAD-: J6.6 R37.1
ASIG_ILOAD_3V: R39.1 U15.6(OUT)
ASIG_VBUS+: J6.2 RN1.1
ASIG_VBUS-: J6.1 RN1.4
C1RX: U1.87(C1RX/RF0) U8.4(R)
C1TX: U1.88(C1TX/RF1) U8.1(D)
CANH: J2.1 R25.2 U8.7(CANH)
CANL: J2.2 R25.1 U8.6(CANL)
EMCABLE_TERMA: J13.1 R81.2
EMCABLE_TERMB: J13.2 Q3.3(D)
ENC_A: J11.4 R66.1
ENC_B: J11.5 R69.1
ENC_Z: J11.3 R63.1
HALL_U: J11.8 R79.1
HALL_V: J11.7 R76.1
HALL_W: J11.6 R75.1
LASERRNGPWR_15V_INPUT: J10.6 R73.1 R88.2 U22.8(V+)
LASERRNGPWR_15V_SWITCHED: F4.2 Q1.2(S)
MCLR: R4.2 R24.1 U1.13(M\C\L\R\)
OSC1: C6.1 R5.2 R6.2 U1.63(OSC1/CLKIN/RC12) Y2.1
OSC2: C7.1 R6.1 U1.64(OSC2/CLKO/RC15) Y2.2
PHASEA: JR1.2 U3.1(SYNC) U5.2(D) U5.3(Q\)
PHASEB: JR3.2 U5.5(Q) U7.1(SYNC)
PSIGA_10V: J7.2 R51.1
PSIGB_10V: J8.2 R54.1
PWM1H: J12.1 U1.94(PWM1H/RE1)
PWM1L: J12.2 U1.93(PWM1L/RE0)
PWM2H: J12.3 U1.99(PWM2H/RE3)
PWM2L: J12.4 U1.98(PWM2L/RE2)
PWM3H: J12.5 U1.3(PWM3H/RE5)
PWM3L: J12.6 U1.100(PWM3L/RE4)
PWM4L: J12.7 U1.4(PWM4L/RE6)
RB3_ENC_Z: R64.2 R65.1 U1.22(AN3/INDX/CN5/RB3)
RB4_ENC_A: R67.2 R68.1 U1.21(AN4/QEA/CN6/RB4)
RB5_ENC_B: R70.2 R71.1 U1.20(AN5/QEB/CN7/RB5)
RB6_PGEC1: J3.5 U1.26(PGEC1/AN6/OCFA/RB6)
RB7_PGED1: J3.4 U1.27(PGED1/AN7/RB7)
RD0-CANLB: U1.72(OC1/RD0) U8.5(LBK)
RD1-5VPG: C37.1 R20.2 U1.76(OC2/RD1) U7.15(PG)
RD2_GASBYPASS_EN: J14.2 U1.77(OC3/RD2)
RD3_STEPPER_ENABLE: J14.1 U1.78(OC4/RD3)
RD4_HALL_W: C82.1 DN6.3(J) R75.2 U1.81(OC5/CN13/RD4)
RD5_HALL_V: C84.1 DN7.3(J) R76.2 U1.82(OC6/CN14/RD5)
RD6_HALL_U: C85.1 DN8.3(J) R79.2 U1.83(OC7/CN15/RD6)
RD12_LRF_EN: R74.1 U1.79(IC5/RD12) U22.4(IN)
RD13_NFAULT_LRFPOW: R72.2 U1.80(IC6/CN19/RD13) U22.3(F\A\U\L\T\)
RF6_RS232_NINVALID: U1.55(SCK1/INT0/RF6) U9.2(\I\N\V\A\L\I\D)
RF12: U1.40(U\2\C\T\S\/RF12) U10.2(R\E\)
RF13: U1.39(U\2\R\T\S\/RF13) U10.3(DE)
RG12_EMFLT_A: R83.2 U1.96(RG12) U24.1(OUTA)
RG13_EMFLT_B: R85.2 U1.97(RG13) U24.6(OUTB)
RG14_EMFLT_C: R77.2 U1.95(RG14) U23.3(F\A\U\L\T\)
RG15_EMFLT_EN: R80.1 U1.1(RG15) U23.4(IN)
RS232_CTS: J5.4 U9.20(R2IN)
RS232_RTS: J5.2 U9.19(T2OUT)
RS232_RXD: J5.3 U9.8(R1IN)
RS232_TXD: J5.1 U9.7(T1OUT)
RS485_A: J4.2 U10.6(A)
RS485_B: J4.1 U10.7(B)
SOSCI: C5.1 U1.73(PGED2/SOSCI/CN1/RC13) Y1.2
SOSCO: C4.1 U1.74(PGEC2/SOSCO/T1CK/CN0/RC14) Y1.1
U1CTS: U1.47(IC7/U\1\C\T\S\/CN20/RD14) U9.1(R2OUT)
U1RTS: U1.48(IC8/U\1\R\T\S\/CN21/RD15) U9.3(T2IN)
U1RXD: U1.52(U1RX/RF2) U9.6(R1OUT)
U1TXD: U1.51(U1TX/RF3) U9.4(T1IN)
U2RXD: U1.49(U2RX/CN17/RF4) U10.1(RO)
U2TXD: U1.50(U2TX/CN18/RF5) U10.4(DI)
VOFF: U13.1(REF) U15.1(REF) U17.1(REF) U19.1(VBIAS)
N08765: C1.1 C2.1 R1.2 R2.2
N08773: R2.1 U1.85(VCAP)
N14987: JP1.1 R3.2 R4.1 SW1.3 SW1.4
N25385: F5.1 J11.1
N30214: C88.1 DN3.3(J) R63.2 R64.1
N30237: C87.1 DN4.3(J) R66.2 R67.1
N30262: C89.1 DN5.3(J) R69.2 R70.1
N38405: C3.1 JP1.2
N39747: U1.29(VREF+/RA10) U2.5(VREF)
N47726: J3.1 R24.2
N61961: C48.2 C50.1 R30.2 R31.1 U13.2(IN-)
N61969: C50.2 C53.1 R31.2 R36.2 U13.3(IN+)
N62625: C57.2 C59.1 R37.2 R38.1 U15.2(IN-)
N62633: C59.2 C62.1 R38.2 R43.2 U15.3(IN+)
N63303: C66.2 C68.1 R44.2 R45.1 U17.2(IN-)
N63311: C68.2 C71.1 R45.2 R50.2 U17.3(IN+)
N72482: C77.1 DN9.3(J) R55.2 U20.5(INB+)
N72600: R51.2 R52.1 R53.2
N72690: C76.1 DN10.3(J) R52.2 U20.3(INA+)
N72804: R54.2 R55.1 R56.2
N72852: F2.1 J8.1
N75830: F1.1 J7.1
N76571: F3.1 J9.1
N76619: J9.2 R57.2 R58.1
N76675: J9.3 R58.2 R59.1
N76787: C78.1 DN1.3(J) R57.1 U21.3(INA+)
N77226: F4.1 J10.1
N77274: J10.2 R60.2 R62.1
N77330: J10.3 R61.1 R62.2
N77442: C79.1 DN2.3(J) R60.1 U21.5(INB+)
N78880: C45.2 R28.1 U12.1(OUTA) U12.2(INA-)
N79170: RN1.7 RN1.8 U11.3(IN+)
N79174: RN1.5 RN1.6 U11.4(IN-)
N79202: R26.1 RN1.3 U11.1(OUT)
N79426: C45.1 R26.2 R27.1
N79442: C43.1 R27.2 U12.3(INA+)
N79600: C46.1 R28.2 R29.1
N79616: C44.1 R29.2 U12.5(INB+)
N83438: C54.2 R34.1 U14.1(OUTA) U14.2(INA-)
N83538: C54.1 R32.2 R33.1
N83554: C51.1 R33.2 U14.3(INA+)
N83666: C55.1 R34.2 R35.1
N83682: C52.1 R35.2 U14.5(INB+)
N84265: C63.2 R41.1 U16.1(OUTA) U16.2(INA-)
N84365: C63.1 R39.2 R40.1
N84381: C60.1 R40.2 U16.3(INA+)
N84493: C64.1 R41.2 R42.1
N84509: C61.1 R42.2 U16.5(INB+)
N85113: C72.2 R48.1 U18.1(OUTA) U18.2(INA-)
N85213: C72.1 R46.2 R47.1
N85229: C69.1 R47.2 U18.3(INA+)
N85341: C73.1 R48.2 R49.1
N85357: C70.1 R49.2 U18.5(INB+)
N98820: Q1.1(G) U22.5(GATE)
N98894: Q1.3(D) R73.2 U22.6(SENSE)
N99153: C83.1 R74.2 U22.2(TIMER)
N109964: C17.1 C27.1 C28.1 JR2.1 U3.13(INTVCC) U5.6(C\L\R\) U5.7(P\R\E\) U5.8(VCC) U6.6(V+)
N110102: C16.1 R8.1 R9.1 U3.16(FB)
N110130: C16.2 C21.1 C22.1 C23.1 L1.2 R8.2 R12.1 U3.14(BIAS) U4.7(VIN1) U4.8(VIN2)
N110228: R7.2 R10.1 U4.3(SNS)
N110370: C18.2 L1.1 U3.9(SW1) U3.10(SW2) U3.11(SW3)
N110394: C18.1 U3.12(BST)
N110516: R11.1 U3.3(RT)
N110530: C19.1 U3.2(TR/SS)
N110898: C26.1 U4.4(SS)
N110954: C25.1 R12.2 U3.15(PG) U4.5(EN)
N111056: R13.2 R15.1 U3.4(EN/UV)
N111200: U5.1(CLK) U6.1(OUT1)
N111222: R16.1 U6.4(SET)
N111230: U6.5(GRD)
N111288: JR2.2 U6.3(DIV)
N113208: R21.2 R23.1 U7.4(EN/UV)
N113286: D2.C R22.1
N113430: C29.1 R17.1 R18.1 U7.16(FB)
N113814: C31.2 L2.1 U7.9(SW1) U7.10(SW2) U7.11(SW3)
N113838: C31.1 U7.12(BST)
N113850: C30.1 U7.13(INTVCC)
N113978: R19.1 U7.3(RT)
N113992: C32.1 U7.2(TR/SS)
N133871: D1.C R14.1
N137397: JR4.2 U8.8(RS)
N140550: F6.2 Q2.2(S) Q3.1(G) R82.1
N140644: R86.2 R87.1 U24.4(-INB)
N140824: R84.2 R86.1 U24.3(+INA)
N140988: Q2.1(G) U23.5(GATE)
N141012: Q2.3(D) R78.2 U23.6(SENSE)
N141056: C86.1 R80.2 U23.2(TIMER)
N141914: Q3.2(S) R84.1
N143860: F6.1 R81.1
N249678: J10.4 J10.5 R89.1

Pads without a net: J2 4; J3 6; J4 4; J5 6; U1 5 10 11 12 14 17 18 19 23 32 33 38 41 42 43 44 53 54 56 57 58 59 60 61 66 67 68 69 70 71 84 89 90 91 92; U2 1; U3 7; U7 7; U9 11 12 13 14 15 16 17; U13 5 8; U15 5 8; U17 5 8; U19 5; U22 7; U23 7

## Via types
v1: diameter 0.61, hole 0.254, TOP to BOTTOM, 366 vias

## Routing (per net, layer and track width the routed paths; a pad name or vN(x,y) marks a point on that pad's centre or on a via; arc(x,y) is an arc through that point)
3.3V: length 116.9
  TOP w0.254: C9.1 v1(104.56,14.76)
  TOP w0.305: v1(35.57,29.34) 35.56,29.35 U13.7 ; v1(112.34,11.84) 112.05,12.13 C8.1 ; C11.1 97.61,20.35 v1(97.58,20.38) ; v1(48.52,29.34) 48.51,29.35 U15.7 ; U11.5 v1(25.52,33.09) ; v1(115.64,21.88) 115.59,21.83 C14.1 114.38,19.46 113.87,18.95 R1.1 ; U14.8 v1(39.2,17.69) ; D1.A 80.01,13.03 ; D1.A 78.82,12.11 ; D1.A 77.62,13.03 ; v1(19.06,29.34) 19.05,29.35 U17.7 ; v1(106.25,27.2) 106.08,27.37 C13.1 ; v1(14.05,37.27) C40.1 13.03,37.98 12.99,38.02 U10.8 ; 76.08,8.59 TP3.1 ; TP3.1 78.25,10.76 ; TP3.1 76.08,10.76 ; TP3.1 78.25,8.59 ; U12.8 v1(29.17,20.6) ; R3.1 99.32,12.27 v1(99.14,12.09) ; C15.1 v1(97.61,22.63) ; C80.1 v1(10.24,6.76) ; v1(97.65,16.88) 97.74,16.79 C10.1 ; 83.52,12.25 U4.2 ; JR4.1 v1(9.31,32.88) ; U18.8 v1(19.64,17.69) ; C12.1 97.74,24.16 v1(97.49,24.41) ; U16.8 v1(49.11,17.69) ; C39.1 106.85,9.44 106.93,9.35 J3.2
  PWR w0.305: J6.12 40.79,43.52 ; J6.12 39.06,45.25 ; J6.12 40.79,45.25 ; J6.12 39.06,43.52 ; 76.08,10.76 TP3.1 ; TP3.1 78.25,10.76 ; TP3.1 78.25,8.59 ; TP3.1 76.08,8.59 ; J3.2 107.8,9.28 ; J3.2 106.07,9.28 ; J3.2 106.07,7.55
  PWR w1.143: J6.12 40.05,44.38 40.97,43.46
  BOTTOM w0.254: U1.37 v1(97.58,20.38) ; U1.30 v1(97.65,16.88) ; v1(104.56,14.76) 105.05,14.26 U1.16 ; v1(106.25,27.2) 106.05,27.4 U1.62 ; U1.46 97.96,24.88 v1(97.49,24.41) ; U1.86 v1(115.64,21.88)
  BOTTOM w0.305: v1(21.79,44.09) C75.1 22.25,42.5 U19.3 U19.4 ; DN9.2 v1(26.13,14.87) ; U8.3 v1(13.67,29.11) 13.7,29.15 C38.1 ; C58.1 v1(48.52,29.34) ; U21.8 56.85,11.96 v1(57.61,12.73) C81.1 ; U9.10 94.92,23.93 94.69,24.16 v1(94.44,24.16) C41.1 93.46,23.48 93.65,23.29 U9.9 ; v1(49.11,17.69) 49.15,17.73 C65.1 ; v1(79.67,4.78) R85.1 v1(81.52,4.78) ; v1(18.41,14.86) 18.04,14.49 DN10.2 ; R77.1 v1(76.2,23.47) ; R72.1 v1(64.34,12.6) ; C49.1 v1(35.57,29.34) ; U1.2 112.05,12.13 v1(112.34,11.84) ; v1(39.2,17.69) 39.24,17.73 C56.1 ; DN2.2 v1(40.47,9.16) ; C67.1 v1(19.06,29.34) ; U20.8 11.29,7.18 10.87,6.76 v1(10.24,6.76) ; v1(25.52,33.09) 25.48,33.13 25.48,33.68 25.83,34.04 C42.1 ; C47.1 29.21,20.98 29.17,20.93 v1(29.17,20.6) ; v1(81.06,1.49) R83.1 v1(82.92,1.49) ; R5.1 v1(101.04,33.05) ; DN1.2 29.73,11.22 29.92,11.41 v1(29.92,11.96) ; C74.1 19.68,17.73 v1(19.64,17.69)
  vias: v1(78.44,11.58) v1(79.07,10.95) v1(79.07,9.68) v1(79.71,11.58) v1(79.71,10.31) v1(80.34,10.95) v1(80.98,11.58) v1(80.98,10.31)
5V: length 62.5
  TOP w0.203: U2.4 U2.3 105.69,19.9 v1(105.99,20.2)
  TOP w0.305: DN4.2 109.99,47.26 110,47.25 110.29,47.25 110.55,47.51 v1(110.59,47.51) ; DN5.2 v1(117.41,47.26) ; 115.24,32.05 114.02,32.05 ; 115.24,32.05 115.24,31.35 115.45,31.14 v1(116.15,31.14) ; 115.24,32.05 v1(116.13,32.05) ; 114.02,32.05 F5.2 ; 114.02,32.05 114.88,32.92 v1(116.15,32.92) ; DN3.2 v1(110.56,41.67) ; U7.14 69.41,32.55 v1(69.55,32.41) ; F5.2 113.82,32.87 114.76,33.81 v1(116.15,33.81) ; F5.2 113.82,31.7 115.14,30.38 116.03,30.38 v1(116.15,30.25) ; C29.2 72.94,29.89 72.94,29.89 C34.1 73.86,29.11 73.72,28.97 R20.1 73.85,28.09 v1(74.63,28.09) ; R17.2 v1(71.03,34.5) ; C36.1 49.66,46.44 ; C36.1 47.29,44.98 ; C36.1 49.66,43.53 ; D2.A v1(109.42,38) ; C35.1 v1(75.9,28.85)
  TOP w1.27: C36.1 52.39,44.98 52.42,44.96 53.34,44.96 54.61,43.69 54.61,38.61 52.95,36.94 L2.2
  PWR w0.305: 117.48,24.97 TP4.1 ; TP4.1 117.48,27.15 ; TP4.1 119.65,24.97 ; TP4.1 119.65,27.15
  BOTTOM w0.305: DN7.2 v1(103.24,45.45) ; DN6.2 v1(103.24,40.37) ; DN8.2 v1(113.74,45.45)
  vias: v1(50.8,43.18) v1(50.8,41.91) v1(50.8,40.64) v1(52.07,42.55) v1(52.07,41.27) v1(52.07,40.01)
15V: length 95.9
  TOP w0.305: v1(8.71,18.06) 9.73,18.06 10.94,16.84 F1.2 11.15,17.07 ; 31.57,13.23 31.32,13.49 v1(30.43,13.49) ; 31.57,13.23 v1(31.57,14.5) ; 31.57,13.23 32.36,12.45 F3.2 ; 85.87,41.1 87.51,41.1 87.58,41.17 ; 85.87,41.1 86.18,40.79 v1(86.18,40.14) ; 85.87,41.1 C20.1 ; 18.77,11.18 17.73,12.22 v1(16.59,12.22) ; 18.77,11.18 v1(16.61,11.18) ; 18.77,11.18 19.1,11.18 ; F2.2 v1(19.81,13.36) ; F2.2 19.41,11.18 ; F2.2 20.24,11.18 21.16,12.09 v1(21.16,13.36) ; R21.1 v1(73.62,41.41) ; C20.1 v1(84.53,40.14) ; C20.1 83.06,41.1 ; 83.06,41.1 82.75,40.79 v1(82.75,40.14) ; 83.06,41.1 82.58,41.1 ; U3.5 88.22,42.32 87.83,41.94 ; U7.6 67.91,39.26 67.89,39.27 ; R13.1 86.07,47.38 v1(86.31,47.14) 86.94,46.51 JR1.1 ; 82.58,41.1 v1(81.4,41.1) ; 82.58,41.1 82.37,41.31 v1(82.37,42.06) ; v1(12.27,19.67) 12.27,18.82 11.15,17.7 ; 68.28,39.27 68.41,39.14 U7.5 ; 19.41,11.18 18.49,12.09 v1(18.49,13.36) ; 19.41,11.18 19.1,11.18 ; v1(66.87,41.17) 67.39,41.17 67.82,41.61 C33.1 ; 19.1,11.18 18.11,10.19 v1(16.59,10.19) ; JR3.1 v1(73.7,39.74) ; 11.15,17.07 12.27,18.19 v1(13.41,18.19) ; 11.15,17.07 11.15,17.53 ; v1(66.87,44.73) 67.51,44.73 67.82,44.42 ; 67.82,44.79 68.15,45.11 v1(68.78,45.11) ; 67.82,44.79 67.82,44.42 ; 67.82,44.79 v1(67.82,46.08) ; U3.6 88.23,41.82 88.09,41.68 ; 11.15,17.7 11.15,17.83 11.13,17.86 v1(11.13,19.67) ; 11.15,17.7 11.15,17.53 ; v1(9.98,19.67) 9.98,18.69 11.15,17.53 ; 67.82,44.42 C33.1 ; C33.1 v1(66.87,42.95) ; v1(36.14,13.49) 35.38,13.49 34.87,12.98 ; F3.2 34.34,12.45 34.87,12.98 ; F3.2 v1(33.27,14.5) ; 34.87,12.98 v1(34.87,14.5)
  TOP w0.508: U23.8 v1(68.4,18.19) R78.1 v1(67.41,19.15)
  PWR w0.305: J1.1 78.15,43.19 ; J1.1 75.96,43.19 ; J1.1 78.15,45.37 ; J1.1 75.96,45.37 ; TP1.1 80.54,37.04 ; TP1.1 80.54,39.21 ; TP1.1 78.36,37.04 ; TP1.1 78.36,39.21
  PWR w1.27: J6.10 35.93,46.67
  BOTTOM w0.305: R88.1 v1(49.74,4.09) ; R88.1 v1(48.83,2.85) ; R88.1 v1(48.83,5.25) ; U24.5 v1(73.08,10.92)
GND_EARTH: length 51.7
  TOP w1.016: J4.3 3.69,36.15 3.51,35.97 3.51,24.4 ; 3.51,24.4 J2.3 ; 3.51,24.4 3.51,6.63
  BOTTOM w0.203: J2.3 5.49,24.4 5.48,24.41 4.27,24.41 3.63,25.04 3.63,35.33 4.45,36.15 J4.3
GND_SIGNAL: length 383.9
  TOP w0.203: v1(101.35,22.63) 102.26,22.63 102.62,22.99 R65.2 ; 74.63,32.99 74.63,32.25 74,31.63 ; R68.2 103,30.96 v1(102.69,31.27) ; U2.2 v1(105.99,18.95)
  TOP w0.305: U3.17 90.68,40.84 90.67,40.82 U3.8 89.36,40.28 ; 65.77,28.09 C30.2 66.74,26.97 ; 91.75,47.92 R15.2 ; R15.2 90.91,49.05 ; R15.2 92.6,49.05 ; C21.2 v1(85.93,17.81) ; 84.28,14.5 84.4,14.5 84.66,14.25 84.89,14.25 85.01,14.12 v1(85.55,14.12) ; 84.28,14.5 U4.9 ; 84.28,14.5 84.68,14.91 v1(85.55,14.91) ; C51.2 36.14,24.02 v1(36.45,23.71) 36.79,23.37 U14.4 ; 84.76,43.08 R11.2 83.07,43.08 ; U15.4 45.97,34.62 45.67,34.32 v1(45.42,34.32) ; J1.2 79.92,43.42 ; J1.2 79.92,45.14 ; J1.2 78.19,45.14 ; J1.2 78.19,43.42 ; C8.2 v1(114.76,13.36) ; U16.4 46.7,23.37 v1(46.35,23.71) 46.05,24.02 C60.2 ; 101.68,48.38 C25.2 102.8,47.41 ; U7.17 66.94,36.79 66.91,36.82 U7.8 ; R22.2 v1(106.29,36.13) ; R9.2 93.68,48.61 ; R9.2 93.68,46.92 ; R9.2 92.55,47.76 ; C15.2 v1(101.35,22.63) ; 65.41,47.33 TP2.1 ; TP2.1 65.41,49.5 ; TP2.1 67.58,47.33 ; TP2.1 67.58,49.5 ; 81.43,35.4 C20.2 ; C20.2 84.53,34.48 ; C20.2 84.53,36.32 ; C20.2 87.63,35.4 ; U4.9 82.25,14.5 81.89,14.86 C24.2 v1(80.98,16.15) 80.98,16.69 81.29,17 R14.2 ; U4.9 84.02,14.75 U4.6 ; v1(75.24,17.17) 75.57,17.5 U23.1 ; C9.2 v1(106.16,14.76) ; JR4.3 v1(13.05,32.9) ; C88.2 110.24,43.18 v1(110.41,43.36) ; C10.2 v1(101.42,16.79) ; 99.39,39.68 C17.2 100.51,40.66 ; U13.4 v1(33.02,34.26) ; C69.2 16.59,24.02 v1(16.89,23.71) 17.24,23.37 U18.4 ; 73.49,24.68 C37.2 74.47,25.81 ; DN3.1 v1(110.65,40.37) ; U17.4 16.51,34.37 v1(16.21,34.06) ; U7.8 66.37,38.13 ; U7.8 66.91,39.25 ; v1(57.43,2.97) C83.2 ; C11.2 v1(100.44,19.41) ; J3.3 104.94,9.35 105.24,9.66 C39.2 ; C23.2 84.21,31.98 ; C23.2 82.75,29.61 ; C23.2 82.75,34.34 ; C23.2 81.3,31.98 ; v1(101.35,24.92) 101.35,24.46 101.05,24.16 C12.2 ; C36.2 60.56,44.98 ; C36.2 58.19,43.53 ; C36.2 58.19,46.44 ; C36.2 55.82,44.98 ; U10.5 v1(11.04,40.5) ; R10.2 v1(85.98,9.86) ; C13.2 107.68,27.37 v1(107.52,27.2) ; C22.2 v1(85.8,19.96) ; C33.2 62.12,46.05 ; C33.2 61.2,42.95 ; C33.2 62.12,39.86 ; C33.2 63.05,42.95 ; 74.01,35.73 R23.2 ; R23.2 75.13,34.88 ; R23.2 76.26,35.73 ; R23.2 75.13,36.57 ; R18.2 74.37,34.5 ; C80.2 v1(13.92,6.76) ; C43.2 v1(23.56,26.81) ; R71.2 v1(117.14,48.95) ; 71.7,44.44 C32.2 72.83,43.47 ; v1(28.07,39.62) 27.83,39.39 RN1.2 ; C87.2 109.64,49.28 v1(110.36,49.28) ; 83.04,45.11 C19.2 84.01,46.23 ; C2.2 111.54,24.07 111.56,24.06 C1.2 112.73,23.14 v1(112.85,23.27) 113.02,23.43 C14.2 ; SW1.1 v1(90.92,14.67) ; v1(30.66,34.04) U11.2 ; 69.67,42.73 R19.2 69.67,44.42 ; C35.2 75.9,32.89 ; C35.2 77.02,31.91 ; C35.2 75.61,31.63 C34.2 ; DN5.1 v1(117.42,45.96) ; SW1.2 90.92,23.59 90.95,23.62 v1(90.95,24.16) ; U22.1 v1(58.97,5.91) ; C40.2 v1(11.98,35.67) ; DN4.1 v1(110.82,45.96) ; U12.4 v1(27.22,27.33) ; C26.2 v1(88.47,14.87)
  TOP w0.381: DN5.1 116.19,45.36 115.99,45.16 C89.2
  TOP w0.635: 91.73,47.61 JR1.3 91.73,45.4 ; 73.57,36 JR3.3 71.36,36 ; 66.44,35.97 U7.17 70.88,35.97 ; 91.52,40.35 U3.17 91.52,44.79
  GND1 w0.305: 65.41,47.33 TP2.1 ; TP2.1 65.41,49.5 ; TP2.1 67.58,47.33 ; TP2.1 67.58,49.5 ; 34.46,7.28 J9.4 ; J9.4 34.46,5.55 ; J9.4 36.18,5.55 ; J14.3 83.35,5.55 ; J14.3 81.62,5.55 ; J14.3 83.35,7.28 ; 92.51,5.55 J5.5 94.23,5.55 ; 78.19,45.14 J1.2 ; J1.2 78.19,43.42 ; J1.2 79.92,43.42 ; J1.2 79.92,45.14 ; 104.07,9.28 J3.3 ; J3.3 105.8,9.28 ; J3.3 104.07,7.55 ; 37.06,45.25 J6.11 ; J6.11 37.06,43.52 ; J6.11 38.79,45.25 ; J8.3 21.72,7.28 ; J8.3 20,7.28 ; J8.3 20,5.55 ; J8.3 21.72,5.55 ; 33.06,45.25 J6.9 ; J6.9 34.79,45.25 ; J6.9 33.06,43.52 ; 81.35,5.55 J14.4 79.62,7.28 ; 5.55,16.51 J7.3 ; J7.3 7.28,16.51 ; J7.3 7.28,14.79 ; J7.3 5.55,14.79 ; J12.8 121.62,13.26 ; J12.8 121.62,14.98 ; J12.8 119.9,13.26 ; 117.9,34.99 J11.2 117.9,33.26
  GND2 w0.305: TP2.1 67.58,47.33 ; TP2.1 65.41,49.5 ; TP2.1 65.41,47.33 ; TP2.1 67.58,49.5 ; J8.3 21.72,5.55 ; J8.3 21.72,7.28 ; J8.3 20,5.55 ; J8.3 20,7.28 ; J6.11 38.79,45.25 ; J6.11 37.06,43.52 ; J6.11 38.79,43.52 ; J6.11 37.06,45.25 ; 81.35,5.55 J14.4 79.62,7.28 ; 81.62,5.55 J14.3 ; J14.3 83.35,7.28 ; J14.3 83.35,5.55 ; 34.46,5.55 J9.4 ; J9.4 34.46,7.28 ; J9.4 36.18,5.55 ; 117.9,34.99 J11.2 ; J11.2 119.62,33.26 ; J11.2 117.9,33.26 ; 33.06,45.25 J6.9 ; J6.9 33.06,43.52 ; J6.9 34.79,43.52 ; J6.9 34.79,45.25 ; J12.8 121.62,13.26 ; J12.8 121.62,14.98 ; J12.8 119.9,14.98 ; J12.8 119.9,13.26 ; 104.07,9.28 J3.3 ; J3.3 105.8,9.28 ; J3.3 105.8,7.55 ; J3.3 104.07,7.55 ; 78.19,43.42 J1.2 ; J1.2 78.19,45.14 ; J1.2 79.92,45.14 ; J1.2 79.92,43.42 ; 92.51,7.28 J5.5 ; J5.5 92.51,5.55 ; J5.5 94.23,5.55 ; 5.55,14.79 J7.3 ; J7.3 7.28,14.79 ; J7.3 7.28,16.51 ; J7.3 5.55,16.51
  BOTTOM w0.203: v1(74.88,34.57) 74.39,34.08 R16.2
  BOTTOM w0.254: v1(106.16,14.76) 105.55,14.15 U1.15 ; v1(100.08,18.03) 100.08,17.63 99.82,17.38 U1.31 ; v1(107.52,27.2) 107.55,27.24 U1.65 ; U5.4 v1(81.1,28.98) ; v1(101.35,24.92) 100.81,24.38 U1.45 ; U1.28 v1(101.42,15.88) ; U1.36 99.98,19.88 100.44,19.42 v1(100.44,19.41)
  BOTTOM w0.305: C42.2 v1(30.66,34.04) ; R61.2 v1(44.91,15.39) ; U19.2 22.18,41.55 C75.2 v1(21.79,39.9) ; C84.2 105.47,47.13 105.11,46.76 104.94,46.76 104.93,46.75 DN7.1 v1(103.08,46.75) ; DN2.1 v1(40.5,7.86) ; C52.2 v1(40.3,18.2) ; C85.2 v1(113.09,49.8) ; v1(15.19,17.04) 14.94,17.3 C76.2 ; DN10.1 18.2,15.79 v1(18.41,16) ; U9.18 86.03,10.65 85.98,10.6 v1(85.98,9.86) ; v1(110.82,45.96) 110.82,46.51 111.06,46.75 DN8.1 ; DN9.1 v1(24.83,14.87) ; C58.2 v1(45.09,30.86) ; v1(53.92,4.09) R89.2 v1(53.02,5.22) ; U6.2 v1(84.61,33.48) ; v1(78.31,25.43) C27.2 C28.2 ; C66.1 16.73,38.99 16.33,38.59 C71.2 v1(15.37,39.85) ; JR2.3 v1(84.75,31.74) ; C3.2 v1(99.26,5.19) ; U1.75 v1(113.12,28.55) 114.36,29.79 C4.2 ; U9.5 v1(88.57,23.62) ; C47.2 v1(29.21,24.23) ; C78.2 v1(27.89,7.52) ; C77.2 v1(22.86,14.33) ; v1(30.22,38.59) C53.2 32.84,38.59 33.24,38.99 C48.1 ; U20.4 v1(14.05,12.98) ; C57.1 v1(51.77,38.76) ; C74.2 v1(19.68,21.46) ; U24.2 68.55,10.92 v1(68.28,11.2) ; C79.2 v1(41.74,6.62) ; v1(76.91,14.88) 76.12,14.1 R87.2 ; U8.2 v1(12.4,29.11) 12.1,29.4 C38.2 ; v1(76.91,16.66) 77.44,16.66 77.85,17.07 C86.2 ; C62.2 v1(44.02,38.76) ; C6.2 v1(102.69,31.27) ; C5.2 109.69,31.27 C7.2 108.45,30.42 v1(108.38,30.35) ; R59.2 v1(43.11,12.84) ; v1(33.53,29.34) 33.77,29.58 C49.2 ; C61.2 v1(50.2,18.2) ; v1(17.02,29.34) 17.26,29.58 C67.2 ; R56.1 v1(17.88,8.51) ; v1(103.2,41.67) DN6.1 105.06,41.67 105.6,42.21 C82.2 ; DN1.1 v1(30.03,9.92) ; C70.2 v1(20.74,18.2) ; R53.1 v1(8.4,16.48) ; C44.2 v1(30.19,20.99) ; C81.2 v1(61.29,12.73) ; U21.4 v1(61.16,7.9) ; v1(75.24,17.17) R82.2 ; C56.2 v1(39.24,21.46) ; C41.2 v1(90.95,24.16) ; C65.2 v1(49.15,21.46)
  BOTTOM w0.381: R82.2 76.33,18.03 76.46,17.9 C86.2
  vias: v1(56.52,42.55) v1(57.15,41.27) v1(57.78,42.55) v1(58.42,41.27) v1(59.05,42.55) v1(59.69,41.27) v1(60.33,42.55) v1(61.59,28.57) v1(62.23,27.3) v1(62.87,28.57) v1(63.5,27.3) v1(64.14,40.01) v1(64.14,38.73) v1(64.14,37.47) v1(64.14,36.2) v1(64.14,28.57) v1(64.77,27.3) v1(65.41,39.37) v1(65.41,38.1) v1(65.41,36.83) v1(70.48,45.72) v1(71.12,46.99) v1(71.75,45.72) v1(72.39,46.99) v1(73.03,45.72) v1(75.56,26.67) v1(75.56,25.4) v1(76.2,26.04) v1(76.83,36.2) v1(76.83,34.92) v1(76.83,26.67) v1(76.83,25.4) v1(77.47,46.35) v1(77.47,41.91) v1(77.47,36.83) v1(77.47,35.56) v1(78.11,47.62) v1(78.11,40.64) v1(78.74,46.35) v1(78.74,41.91) v1(79.38,47.62) v1(79.38,40.64) v1(80.01,46.35) v1(80.01,41.91) v1(83.19,48.26) v1(83.19,46.99) v1(83.82,47.62) v1(84.45,48.26) v1(84.45,46.99) v1(90.17,39.37) v1(90.17,38.1) v1(90.81,38.73) v1(91.44,39.37) v1(91.44,38.1) v1(93.42,49.17) v1(94.44,49.17) v1(98.76,49.05) v1(99.77,49.05) v1(100.33,38.1) v1(100.33,36.83) v1(100.97,37.47) v1(101.6,38.1) v1(101.6,36.83)
AN0_LOADCELL: length 51.6
  INR1 w0.203: v1(59.13,7.9) 59.13,8.43 60.48,9.78 63.93,9.78 66.93,12.78 72.07,12.78 72.4,13.11 99.6,13.11 100.28,12.43 v1(100.28,11.89)
  BOTTOM w0.203: 59.77,10.19 59.82,10.13 U21.2 ; 59.77,10.19 59.13,9.55 v1(59.13,7.9) ; 59.77,10.19 59.77,10.44 60.11,10.78 U21.1 ; U1.25 100.55,12.17 v1(100.28,11.89)
AN1_POSITION: length 54.7
  INR1 w0.203: v1(101.28,11.84) 101.28,12.37 100.14,13.51 72.23,13.51 71.9,13.18 66.7,13.18 63.7,10.19 59.26,10.19 58.55,9.48 v1(55.01,9.48)
  BOTTOM w0.203: U1.24 101.05,12.06 v1(101.28,11.84) ; U21.6 v1(55.01,9.48) 54.99,9.5 54.99,9.98 55.14,10.13 U21.7
AN10_DIFFPB: length 99.6
  INR1 w0.203: v1(13.79,10.19) 14.75,10.19 15.67,11.11 15.67,15.59 17,16.92 18.49,16.92 20.52,14.88 22.17,14.88 23.06,15.77 37.13,15.77 39.32,13.59 62.69,13.59 64.29,15.19 72.27,15.19 72.59,15.52 89.05,15.52 89.08,15.49 v1(90.12,16.54)
  BOTTOM w0.203: 12.65,10.19 12.59,10.13 U20.6 ; 12.65,10.19 v1(13.79,10.19) ; 12.65,10.19 12.15,10.19 11.94,9.98 U20.7 ; v1(90.12,16.54) 92.46,18.88 U1.34
AN11_TORQ_DIFFPA: length 100.9
  INR1 w0.203: v1(88.98,16.54) 88.21,16.54 87.6,15.93 84,15.93 82.91,17.02 78.66,17.02 77.57,15.93 72.42,15.93 72.1,15.6 64.12,15.6 62.52,14 39.49,14 37.3,16.18 22.89,16.18 22,15.29 20.69,15.29 18.66,17.32 16.83,17.32 15.27,15.76 15.27,11.53 15.06,11.33 v1(13.79,11.33)
  BOTTOM w0.203: 12.01,11.33 11.94,11.4 U20.2 ; 12.01,11.33 v1(13.79,11.33) ; 12.01,11.33 11.63,11.33 11.29,11.67 U20.1 ; v1(88.98,16.54) 91.82,19.38 U1.35
AN16_VSENSE: length 104.5
  TOP w0.203: 27.89,23.13 C46.2 v1(25.15,21.67) ; 27.89,23.13 27.89,22.82 27.87,22.8 U12.6 ; 27.89,23.13 28.19,23.13 28.4,22.93 28.4,22.92 28.52,22.8 U12.7
  INR1 w0.203: v1(95,15.83) 95.38,16.21 95.38,17.17 94.26,18.29 89,18.29 88.47,18.82 74.75,18.82 74.63,18.69 72.21,18.69 70.69,20.22 55.83,20.22 53.42,22.63 31.57,22.63 30.61,21.67 v1(25.15,21.67)
  BOTTOM w0.203: U1.6 110.05,10.69 108.97,9.6 97.56,9.6 95.83,11.33 95.83,14.12 95,14.96 v1(95,15.83)
AN17_IBUS: length 94.3
  TOP w0.203: 37.9,20.54 38.25,20.54 38.55,20.23 U14.7 ; 37.9,20.54 U14.6 ; 37.9,20.54 36.4,20.54 36.2,20.34 C55.2 v1(35.18,19.13)
  INR1 w0.203: v1(35.18,19.13) 35.18,20.65 36.6,22.07 52.07,22.07 54.75,19.39 66.8,19.39 66.8,19.4 67.15,19.76 67.66,19.76 68.02,19.4 68.02,19.39 70.41,19.39 71.66,18.15 74.88,18.15 75.15,18.41 88.11,18.41 88.85,17.68 93.55,17.68 v1(94.56,16.66)
  BOTTOM w0.203: U1.7 109.55,11.08 108.48,10.01 98.04,10.01 96.34,11.71 96.34,14.63 95.61,15.37 95.61,16.23 95.17,16.66 v1(94.56,16.66)
AN18_ILOAD: length 81
  TOP w0.203: U16.7 48.46,20.23 48.15,20.54 47.81,20.54 ; v1(45.09,18.87) C64.2 46.1,20.34 46.3,20.54 47.81,20.54 ; 47.81,20.54 U16.6
  INR1 w0.203: v1(96.22,15.9) 95.33,15.01 93.68,15.01 91.49,17.2 84.91,17.2 84.33,17.78 77.01,17.78 75.64,16.41 72.09,16.41 71.07,17.42 55.32,17.42 53.87,18.87 v1(45.09,18.87)
  BOTTOM w0.203: U1.8 109.05,11.59 107.87,10.41 98.53,10.41 96.85,12.09 96.85,15.27 v1(96.22,15.9)
AN19_IBOOST: length 109.3
  TOP w0.203: C73.2 16.64,20.34 16.84,20.54 v1(17.35,20.54) 18.34,20.54 ; 18.34,20.54 U18.6 ; 18.34,20.54 18.69,20.54 18.99,20.23 U18.7
  INR1 w0.203: v1(96.09,18.19) 95.33,18.19 94.82,18.69 89.87,18.69 89.3,19.27 85.1,19.27 84.3,20.07 72.11,20.07 71.07,21.11 58.12,21.11 54.31,24.92 28.27,24.92 27.13,23.77 24.21,23.77 v1(23.44,23.01)
  BOTTOM w0.203: v1(23.44,23.01) 19.82,23.01 v1(17.35,20.54) ; U1.9 108.55,12.24 107.13,10.82 99.01,10.82 97.36,12.47 97.36,16.15 96.09,17.42 v1(96.09,18.19)
ASIG_IBOOST+: length 21.8
  TOP w0.203: R50.1 17.65,40.12 18.24,40.7 18.24,44.6 20.9,47.27 30.43,47.27 31.19,46.51 31.19,45.12 J6.8
ASIG_IBOOST-: length 20.5
  TOP w0.203: R44.1 19.27,40.14 18.64,40.77 18.64,44.43 21.07,46.86 30.26,46.86 30.78,46.34 30.78,45.24 J6.7
ASIG_IBOOST_3V: length 3.2
  TOP w0.203: R46.1 17.67,28.85 17.78,28.96 U17.6
ASIG_IBUS+: length 3.1
  TOP w0.203: J6.3 34.72,41.59 34.72,40.68 34.16,40.12 R36.1
ASIG_IBUS-: length 3.1
  TOP w0.203: J6.4 35.13,41.58 35.13,40.79 35.78,40.14 R30.1
ASIG_IBUS_3V: length 6.2
  TOP w0.203: U13.6 34.29,28.96 34.18,28.85 34.18,27.81 R32.1
ASIG_ILOAD+: length 14.2
  BOTTOM w0.203: R43.1 47.05,42.56 47.55,43.05 47.55,43.67 47.4,43.81 45.14,43.81 41.39,40.07 39.47,40.07 38.78,40.75 38.78,41.52 J6.5
ASIG_ILOAD-: length 14.2
  BOTTOM w0.203: J6.6 39.19,41.65 39.19,40.92 39.64,40.47 41.16,40.47 44.91,44.22 47.57,44.22 47.96,43.84 47.96,43.21 48.61,42.56 R37.1
ASIG_ILOAD_3V: length 3.2
  TOP w0.203: U15.6 47.24,28.96 47.13,28.85 R39.1
ASIG_VBUS+: length 6.2
  TOP w0.203: RN1.1 28.73,39.71 29.16,40.13 31.04,40.13 31.93,41.02 J6.2
ASIG_VBUS-: length 6.9
  TOP w0.203: RN1.4 26.13,39.92 26.75,40.54 29.41,40.54 29.92,41.05 J6.1
C1RX: length 110.7
  INR1 w0.203: v1(22.05,27.97) 22.81,28.73 54.26,28.73 60.4,22.59 76.35,22.59 76.95,22 v1(105.11,22)
  BOTTOM w0.203: U1.87 112.62,21.38 108.15,16.92 105.31,16.92 105.11,17.12 v1(105.11,22) ; U8.4 14.94,26.96 15.44,26.45 16.65,26.45 18.17,27.97 v1(22.05,27.97)
C1TX: length 115
  INR1 w0.203: v1(104.47,21.23) 103.2,21.23 102.95,21.49 97.23,21.49 97.18,21.54 76.83,21.54 76.18,22.18 60.09,22.18 54.05,28.22 23.72,28.22 22.58,27.08 v1(22.05,27.08)
  BOTTOM w0.203: v1(104.47,21.23) 104.47,16.85 104.81,16.51 108.32,16.51 112.69,20.88 U1.88 ; v1(22.05,27.08) 19,27.08 17.75,25.83 11.38,25.83 11.13,26.09 U8.1
CANH: length 8.1
  TOP w0.203: J2.1 9.34,24.4 9.37,24.42 R25.2
  BOTTOM w0.203: J2.1 9.34,24.4 9.35,24.41 11.9,24.41 12.4,23.91 U8.7
CANL: length 10.2
  TOP w0.203: J2.2 9.35,26.4 9.37,26.43 R25.1
  BOTTOM w0.203: U8.6 13.67,23.91 12.66,24.92 9.9,24.92 J2.2
